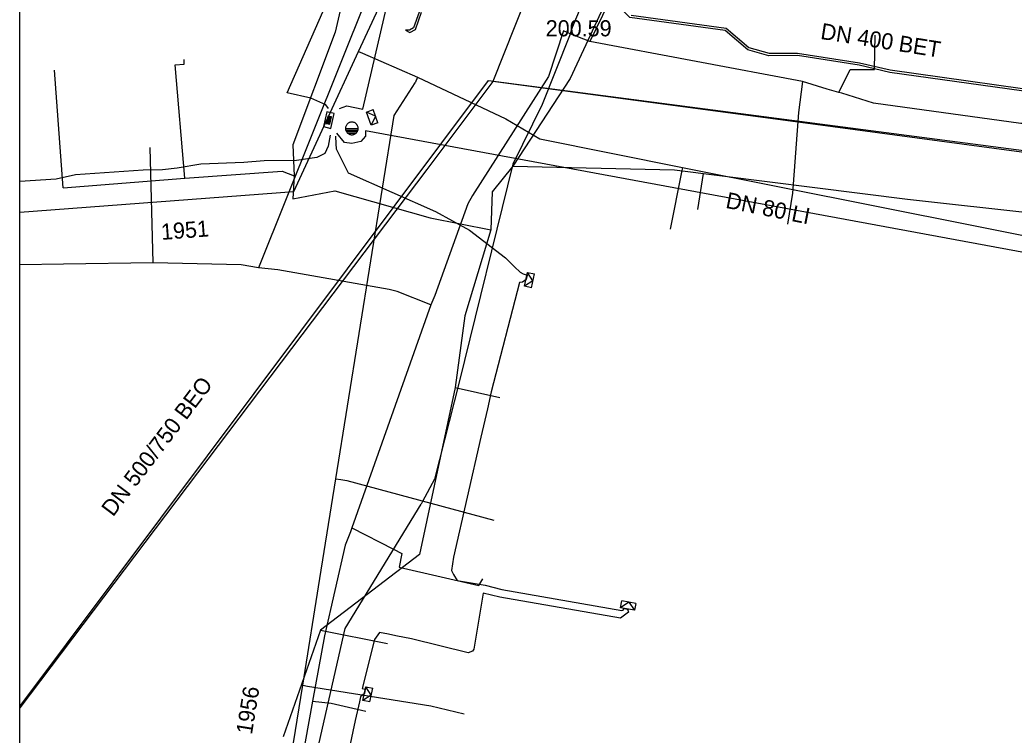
# Model space of a CAD drawing. Extents: x -596024 to -594475, y -1163820 to -1161957.
# Drawn here: x -596024.42 to -595975.05, y -1162923.14 to -1162887.64 of the extents above; entities that cross this region are included whole.
import ezdxf

# ---------------------------------------------------------------- set-up
doc = ezdxf.new("R2010")
doc.units = 0
for name, color, linetype in [('13', 7, 'Continuous'), ('31', 7, 'Continuous'), ('Level 1', 7, 'Continuous'), ('Vrstva 12', 7, 'Continuous'), ('Vrstva 13', 7, 'Continuous'), ('Vrstva 15', 7, 'Continuous'), ('Vrstva 16', 7, 'Continuous'), ('Vrstva 25', 7, 'Continuous'), ('Vrstva 28', 7, 'Continuous'), ('Vrstva 42', 7, 'Continuous'), ('Vrstva 43', 7, 'Continuous'), ('Vrstva 51', 7, 'Continuous'), ('Vrstva 55', 7, 'Continuous'), ('Vrstva 63', 7, 'Continuous'), ('Vrstva 9', 7, 'Continuous')]:
    doc.layers.add(name, color=color, linetype=linetype)

# ---------------------------------------------------------------- blocks, each defined once
blk = doc.blocks.new('NN630')
at = {"layer": '31'}
for points in [[(-0.003, -0.7), (-0.703, 0)], [(-0.703, -0.7), (-0.703, 0), (0.697, 0), (0.697, -0.7)], [(-0.003, -0.7), (0.697, 0)], [(-0.703, -0.7), (0.697, -0.7)]]:
    blk.add_lwpolyline(points, dxfattribs=at)
blk = doc.blocks.new('NN440')
at = {"layer": '13'}
for points in [[(-0.631, 0), (0.629, 0)], [(0.631, -0.004), (0.627, 0.062), (0.617, 0.127), (0.6, 0.191), (0.577, 0.252), (0.547, 0.311), (0.511, 0.366), (0.469, 0.417), (0.423, 0.464), (0.371, 0.505), (0.316, 0.542), (0.257, 0.571), (0.196, 0.595), (0.132, 0.612), (0.067, 0.622), (0.001, 0.626), (-0.065, 0.622), (-0.13, 0.612), (-0.194, 0.595), (-0.255, 0.571), (-0.314, 0.542), (-0.369, 0.505), (-0.42, 0.464), (-0.467, 0.417), (-0.509, 0.366), (-0.544, 0.311), (-0.574, 0.252), (-0.598, 0.191), (-0.615, 0.127), (-0.626, 0.062), (-0.629, -0.004), (-0.626, -0.07), (-0.615, -0.135), (-0.598, -0.199), (-0.574, -0.26), (-0.544, -0.319), (-0.509, -0.374), (-0.467, -0.426), (-0.42, -0.472), (-0.369, -0.514), (-0.314, -0.55), (-0.255, -0.58), (-0.194, -0.603), (-0.13, -0.62), (-0.065, -0.631), (0.001, -0.634), (0.067, -0.631), (0.132, -0.62), (0.196, -0.603), (0.257, -0.58), (0.316, -0.55), (0.371, -0.514), (0.423, -0.472), (0.469, -0.426), (0.511, -0.374), (0.547, -0.319), (0.577, -0.26), (0.6, -0.199), (0.617, -0.135), (0.627, -0.07), (0.631, -0.004)], [(-0.601, -0.177), (0.57, -0.177)], [(-0.513, -0.325), (0.501, -0.325)], [(-0.375, -0.473), (0.353, -0.473)]]:
    blk.add_lwpolyline(points, dxfattribs=at)
blk = doc.blocks.new('NN620')
at = {"layer": 'Vrstva 28'}
for points in [[(0.752, 0.004), (-0.748, 0.004)], [(-0.748, 0.004), (-0.748, -0.746)], [(0.752, -0.746), (0.752, 0.004)], [(-0.748, -0.746), (0.752, -0.746)], [(0.368, -0.18), (-0.376, -0.18)], [(-0.376, -0.18), (-0.376, -0.558)], [(-0.376, -0.558), (0.368, -0.558)], [(0.321, -0.227), (-0.329, -0.227)], [(-0.329, -0.227), (-0.329, -0.51)], [(-0.329, -0.51), (0.321, -0.51)], [(0.274, -0.274), (-0.281, -0.274)], [(-0.281, -0.274), (-0.281, -0.463)], [(-0.281, -0.463), (0.274, -0.463)], [(0.227, -0.321), (-0.234, -0.321)], [(-0.234, -0.321), (-0.234, -0.416)], [(-0.234, -0.416), (0.227, -0.416)], [(-0.193, -0.369), (0.185, -0.369)], [(0.227, -0.416), (0.227, -0.321)], [(0.274, -0.463), (0.274, -0.274)], [(0.321, -0.51), (0.321, -0.227)], [(0.368, -0.558), (0.368, -0.18)]]:
    blk.add_lwpolyline(points, dxfattribs=at)

msp = doc.modelspace()

# ---------------------------------------------------------------- linework, layer by layer
at = {"layer": 'Level 1'}
msp.add_lwpolyline([(-596024.42, -1162921.712), (-596001.15, -1162890.66), (-595962.42, -1162895.72), (-595924.28, -1162893.96), (-595884.16, -1162890.98), (-595845.62, -1162894.68), (-595821.86, -1162890.31), (-595800.89, -1162887.52), (-595750.86, -1162888.83), (-595701.41, -1162888.47), (-595679.74, -1162860.44)], dxfattribs=at)
at = {"layer": 'Vrstva 13'}
for p, q in [((-596007.605, -1162889.215), (-596007.404, -1162889.304)), ((-596007.404, -1162889.304), (-596004.674, -1162890.493)), ((-596004.674, -1162890.493), (-596004.791, -1162890.77))]:
    msp.add_line(p, q, dxfattribs=at)
for points in [[(-596007.605, -1162889.215), (-596006.604, -1162887.048), (-596000.36, -1162873.532), (-595996.26, -1162864.658), (-595995.84, -1162863.749)], [(-596024.42, -1162897.185), (-596010.814, -1162896.161), (-596007.605, -1162889.215)], [(-596004.674, -1162890.493), (-596000.288, -1162892.561), (-595998.61, -1162893.55), (-595991.526, -1162894.965), (-595972.174, -1162898.831), (-595965.329, -1162898.637)], [(-596022.777, -1162997.751), (-596022.415, -1162995.418), (-596018.66, -1162972.098), (-596017.235, -1162963.249), (-596015.572, -1162952.918), (-596013.822, -1162942.049), (-596011.907, -1162930.158), (-596011.481, -1162927.516), (-596010.378, -1162920.665), (-596009.524, -1162915.36), (-596008.729, -1162910.422), (-596005.829, -1162892.382), (-596004.791, -1162890.77)], [(-595991.526, -1162894.965), (-595991.574, -1162895.205), (-595992.139, -1162898.033)], [(-596008.729, -1162910.422), (-596008.477, -1162910.462), (-596008.186, -1162910.509), (-596000.882, -1162912.476)], [(-596010.378, -1162920.665), (-596010.136, -1162920.704), (-596004.009, -1162921.69), (-596002.352, -1162922.081)]]:
    msp.add_lwpolyline(points, dxfattribs=at)
at = {"layer": 'Vrstva 16'}
for points in [[(-595979.35, -1162858.35), (-595979.97, -1162859.14), (-595982.38, -1162861.56), (-595983.92, -1162864.18), (-595987.03, -1162868.22), (-595988.92, -1162871.66), (-595989.87, -1162874.62), (-595990.47, -1162877.04), (-595992.63, -1162881.53), (-595996.12, -1162888.72)], [(-596001.18, -1162872.02), (-596001.24, -1162872.18), (-596005.83, -1162883.15), (-596012.57, -1162899.95)], [(-595983.6, -1162891.28), (-595983.76, -1162891.24), (-595984.34, -1162891.08), (-595985.56, -1162890.7), (-595996.12, -1162888.72), (-595997.1, -1162888.33), (-595997.43, -1162888.19), (-595998.18, -1162890.45), (-596001.94, -1162896.36), (-596002.18, -1162896.77), (-596003.82, -1162901.32), (-596004.01, -1162901.79), (-596005.69, -1162901.12), (-596006.08, -1162901.03), (-596011.62, -1162900.05), (-596012.57, -1162899.95), (-596013.44, -1162899.8), (-596017.8, -1162899.7), (-596022.25, -1162899.77), (-596024.42, -1162899.802)], [(-595983.76, -1162891.24), (-595983.2, -1162890.11), (-595981.99, -1162890.1), (-595981.96, -1162888.4)], [(-595985.56, -1162890.7), (-595985.76, -1162892.24), (-595986.06, -1162896.24), (-595986.31, -1162897.78)], [(-595957.35, -1162893.06), (-595958.15, -1162893.09), (-595965.41, -1162893.27), (-595971.19, -1162892.79), (-595974.72, -1162892.79), (-595982.04, -1162891.78), (-595983.6, -1162891.28)], [(-596017.8, -1162899.7), (-596017.95, -1162893.98)], [(-596004.01, -1162901.79), (-596007.94, -1162912.85), (-596008.01, -1162913.05), (-596008.27, -1162913.72), (-596009.29, -1162918.22), (-596009.89, -1162921.45), (-596010.25, -1162923.47), (-596012.26, -1162933.48), (-596013.37, -1162935.57), (-596014.34, -1162937.31), (-596015.52, -1162944.21), (-596017.05, -1162953.76), (-596018.4, -1162962), (-596020.32, -1162973.27), (-596022.13, -1162984.46), (-596022.3, -1162985.53), (-596023.49, -1162993.99), (-596019.98, -1162994.58), (-596020, -1162995.02)], [(-596007.94, -1162912.85), (-596005.87, -1162913.91), (-596005.46, -1162914.13), (-596005.59, -1162914.8)], [(-596005.59, -1162914.8), (-596001.63, -1162915.71), (-596001.43, -1162915.38)], [(-596009.89, -1162921.45), (-596008.97, -1162921.56), (-596007.24, -1162921.95)]]:
    msp.add_lwpolyline(points, dxfattribs=at)
at = {"layer": 'Vrstva 25'}
for p, q in [((-595993.752, -1162883.34), (-595997.094, -1162890.56)), ((-596007.856, -1162884.19), (-596008.758, -1162888.246)), ((-596008.758, -1162888.246), (-596010.859, -1162893.848)), ((-596016.703, -1162889.881), (-596016.27, -1162889.841)), ((-596016.227, -1162895.494), (-596016.703, -1162889.881)), ((-596016.27, -1162889.841), (-596016.269, -1162889.604)), ((-596022.266, -1162895.973), (-596022.704, -1162890.144)), ((-595997.094, -1162890.56), (-595999.938, -1162894.911)), ((-596010.859, -1162893.848), (-596010.794, -1162895.376)), ((-595999.938, -1162894.911), (-596000.963, -1162896.18)), ((-595999.938, -1162894.911), (-595991.919, -1162895.084)), ((-596016.227, -1162895.494), (-596011.403, -1162895.149)), ((-596011.403, -1162895.149), (-596010.794, -1162895.376)), ((-596010.794, -1162895.376), (-596010.864, -1162896.52)), ((-595991.919, -1162895.084), (-595980.341, -1162896.549)), ((-595990.75, -1162897.049), (-595990.471, -1162895.267)), ((-596022.266, -1162895.973), (-596016.227, -1162895.494)), ((-596010.864, -1162896.52), (-596008.776, -1162896.128)), ((-596008.776, -1162896.128), (-596004.043, -1162897.47)), ((-596000.963, -1162896.18), (-596001.028, -1162898.071)), ((-595980.341, -1162896.549), (-595969.086, -1162897.783)), ((-596004.043, -1162897.47), (-596001.028, -1162898.071)), ((-596001.028, -1162898.071), (-596002.333, -1162902.336)), ((-596002.333, -1162902.336), (-596002.804, -1162905.895)), ((-596002.804, -1162905.895), (-596004.58, -1162914.173)), ((-596002.804, -1162905.895), (-596000.589, -1162906.386)), ((-596004.58, -1162914.173), (-596009.487, -1162917.937)), ((-596009.487, -1162917.937), (-596011.341, -1162923.219)), ((-596009.487, -1162917.937), (-596006.165, -1162918.585))]:
    msp.add_line(p, q, dxfattribs=at)
at = {"layer": 'Vrstva 42'}
for points in [[(-596009.094, -1162892.042), (-596009.221, -1162891.854), (-596009.974, -1162891.525), (-596011.152, -1162891.264), (-596005.217, -1162877.806), (-596003.217, -1162873.325), (-596004.035, -1162872.905)], [(-596009.013, -1162893.368), (-596009.115, -1162893.906), (-596009.277, -1162894.281), (-596009.679, -1162894.476), (-596010.681, -1162894.616), (-596012.291, -1162894.641), (-596013.296, -1162894.714), (-596015.439, -1162894.803), (-596016.609, -1162895.009), (-596017.346, -1162895.079), (-596018.297, -1162895.109), (-596021.664, -1162895.328), (-596022.62, -1162895.548), (-596024.42, -1162895.662)], [(-596008.753, -1162893.416), (-596008.732, -1162893.791), (-596008.717, -1162894.038), (-596008.114, -1162895.238), (-596003.789, -1162897.161), (-596002.092, -1162898.076), (-596000.306, -1162899.453), (-595999.857, -1162899.9), (-595999.574, -1162900.164), (-595999.427, -1162900.25), (-595999.237, -1162900.319), (-595999.287, -1162900.523), (-595999.469, -1162900.664), (-595999.616, -1162900.675), (-596001.026, -1162906.098), (-596001.207, -1162906.949), (-596001.531, -1162908.35), (-596002.885, -1162914.309), (-596002.983, -1162914.972), (-596002.888, -1162915.171), (-596002.706, -1162915.473), (-596001.321, -1162915.701), (-596000.491, -1162915.906), (-595994.53, -1162916.948), (-595994.468, -1162916.943), (-595994.439, -1162916.85), (-595994.246, -1162916.883), (-595994.193, -1162917.034), (-595994.598, -1162917.342), (-596000.593, -1162916.301), (-596001.421, -1162916.089), (-596001.879, -1162918.868), (-596001.944, -1162918.969), (-596002.169, -1162919.055), (-596004.977, -1162918.359), (-596005.751, -1162918.21), (-596006.111, -1162918.13), (-596006.563, -1162918.039), (-596006.815, -1162918.387), (-596007.418, -1162920.829), (-596007.272, -1162920.866), (-596007.314, -1162921.076), (-596007.503, -1162921.239), (-596007.554, -1162921.491), (-596007.77, -1162922.41), (-596009.279, -1162929.535)], [(-596007.253, -1162893.155), (-596007.256, -1162893.419), (-596007.493, -1162893.673), (-596007.932, -1162893.782), (-596008.306, -1162893.729), (-596008.678, -1162893.272)]]:
    msp.add_lwpolyline(points, dxfattribs=at)
at = {"layer": 'Vrstva 51'}
for points in [[(-596007.395, -1162892.082), (-596000.64, -1162863.06), (-595974.33, -1162850.4), (-595952.132, -1162843.38), (-595950.14, -1162842.76)], [(-596008.554, -1162892.036), (-596008.185, -1162891.91), (-596007.395, -1162892.082)], [(-595965.987, -1162900.769), (-596006.361, -1162893.32), (-596007.253, -1162893.155)]]:
    msp.add_lwpolyline(points, dxfattribs=at)
at = {"layer": 'Vrstva 55'}
for points in [[(-595972.079, -1162891.529), (-595981.231, -1162890.249), (-595982.751, -1162889.899), (-595985.815, -1162889.41), (-595987.228, -1162889.42), (-595988.279, -1162889.124), (-595989.396, -1162888.167), (-595994.128, -1162887.527), (-595995.109, -1162886.526), (-595995.874, -1162885.874), (-595996.532, -1162885.498), (-595996.57, -1162886.99), (-595996.99, -1162888.03), (-595997.13, -1162888.43), (-595998.48, -1162891.84), (-595999.94, -1162894.81), (-596002.61, -1162905.62), (-596003.83, -1162910.44), (-596004.43, -1162911.55), (-596004.5, -1162911.68)], [(-596004.6, -1162887.26), (-596004.87, -1162888.04), (-596005.08, -1162888.15), (-596005.272, -1162888.147), (-596005.051, -1162888.27), (-596004.772, -1162888.124), (-596004.475, -1162887.265)], [(-595994.072, -1162887.413), (-595989.344, -1162888.053), (-595988.221, -1162889.016), (-595987.212, -1162889.3), (-595985.805, -1162889.29), (-595982.729, -1162889.781), (-595981.209, -1162890.131), (-595972.061, -1162891.411)], [(-595993.737, -1163007.36), (-595991.896, -1163007.08), (-595991.68, -1162999.83), (-596000.4, -1162997.68), (-596012.68, -1162994.73), (-596018.57, -1162992.95), (-596015.38, -1162970.85), (-596018.2, -1162967.54), (-596017.59, -1162962.68), (-596013.46, -1162940.69), (-596008.27, -1162917.84), (-596004.5, -1162911.68)]]:
    msp.add_lwpolyline(points, dxfattribs=at)
at = {"layer": 'Vrstva 63'}
msp.add_lwpolyline([(-594475.47, -1163820.23), (-596024.42, -1163820.23), (-596024.42, -1161956.88), (-594475.47, -1161956.88)], close=True, dxfattribs=at)
at = {"layer": 'Vrstva 9'}
for points in [[(-595991.36, -1162866.6), (-595993.737, -1162872.585), (-596000.93, -1162890.7)], [(-596000.93, -1162890.7), (-596004.213, -1162895.061), (-596024.42, -1162921.783)], [(-595962.17, -1162895.89), (-595969.614, -1162894.893), (-595977.652, -1162893.817), (-595985.165, -1162892.811), (-596000.93, -1162890.7)]]:
    msp.add_lwpolyline(points, dxfattribs=at)

# ---------------------------------------------------------------- block references
at = {"layer": 'Vrstva 43'}
for name, p, xscale, yscale, rotation in [('NN620', (-596009.26, -1162892.578), 0.5, 0.5, 77), ('NN630', (-596007.092, -1162892.544), 0.5, 0.5, 110), ('NN630', (-595999.287, -1162900.523), 0.49999999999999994, 0.5000000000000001, 78), ('NN630', (-595994.246, -1162916.883), 0.5, 0.5, 170), ('NN630', (-596007.314, -1162921.076), 0.49999999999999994, 0.5000000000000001, 78)]:
    msp.add_blockref(name, p, dxfattribs=dict(at, xscale=xscale, yscale=yscale, rotation=rotation))
at = {"layer": 'Vrstva 43', "xscale": 0.5, "yscale": 0.5}
msp.add_blockref('NN440', (-596007.937, -1162893.029), dxfattribs=at)

# ---------------------------------------------------------------- texts
at = {"layer": 'Vrstva 12'}
msp.add_text('200.59', height=0.8, dxfattribs=at).set_placement((-595998.311, -1162888.461))
for s, rotation, p in [('DN 400 BET', 351.0512, (-595984.701, -1162888.585)), ('DN 500/750 BEO', 52.884, (-596019.794, -1162912.338))]:
    msp.add_text(s, height=0.8, rotation=rotation, dxfattribs=at).set_placement(p)
at = {"layer": 'Vrstva 15'}
for s, rotation, p in [('DN 80 LI', 348.7021, (-595989.415, -1162896.967)), ('1951', 4.2972, (-596017.382, -1162898.565)), ('1956', 80.8443, (-596012.899, -1162923.139))]:
    msp.add_text(s, height=0.8, rotation=rotation, dxfattribs=at).set_placement(p)

doc.saveas('drawing.dxf')
